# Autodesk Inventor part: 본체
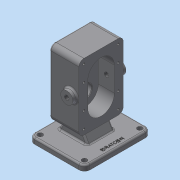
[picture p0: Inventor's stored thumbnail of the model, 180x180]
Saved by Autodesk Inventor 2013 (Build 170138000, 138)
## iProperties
Created: 2020-04
Part Number: 본체
Material: 일반
Document SubType Name: Modeling
Designer: dgall
Density: 1 g/cm^3
Author: dgall
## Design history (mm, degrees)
sketch "스케치1"
  geometry: L1 (-50, 60)-(50, 60); L2 (50, 60)-(50, -60); L3 (50, -60)-(-50, -60); L4 (-50, -60)-(-50, 60); 3 further points
  constraints: 8 end point, 2 midpoint, 2 parallel, 1 horizontal, 1 horizontal alignment, 1 perpendicular, 1 vertical alignment
  dimensions: "d0" = 100 distance of L1.start L1.end; "d2" = 120 distance of L1.end L2.end
extrude "돌출1" new body sketch "스케치1" stored distance "d3" = 10; taper "d4" = 0 deg
node "작업 평면1"
sketch "스케치2"
  geometry: L1 (145, -20)-(25, -20); L2 (25, -20)-(25, -100); L3 (25, -100)-(145, -100); L4 (145, -100)-(145, -20); L5 (-5, -120)-(-5, 0) reference; 2 further points
  constraints: 8 end point, 2 parallel, 1 horizontal, 1 horizontal alignment, 1 midpoint, 1 perpendicular
  dimensions: "d5" = 150 distance between parallel lines of L5 L4; "d6" = 80 distance of L3.end L1.start; "d7" = 120 distance of L1.start L1.end
extrude "돌출2" join sketch "스케치2" distance "d8" = 70; taper "d9" = 0 deg
extrude "돌출3" cut sketch "스케치2" distance "d10" = 17; taper "d11" = 0 deg
sketch "스케치3" dims "d31" = 10, "d38" = 10
  geometry: L1 (-25, -20)-(-145, -20) reference; L2 (-145, -20)-(-145, -100) reference; L3 (-145, -100)-(-25, -100) reference; L4 (-63, -84)-(-107, -84); L5 (-63, -36)-(-107, -36); A1 r 24 centre (-107, -60) between (-107, -36) and (-107, -84); A2 r 24 centre (-63, -60) between (-63, -84) and (-63, -36); 11 further points
  constraints: 4 end point, 4 point on circle, 3 horizontal, 2 centre point, 2 horizontal alignment, 2 midpoint, 2 parallel, 2 tangent, 1 equal radius, 1 vertical, 7 other
  dimensions: "d12" = 48 diameter of A1; "d14" = 44 distance of A2.centre A1.centre; "d15" = 9 distance from line of L2 point (-136, -91); "d16" = 9 distance from line of L3 point (-136, -91); "d17" = 29 horizontal distance of A1.centre point (-136, -91); "d20" = 62 distance of point (-136, -91) point (-136, -29); "d23" = 29 distance of point (-136, -91) point (-107, -91); "d28" = 44 distance of point (-107, -91) point (-63, -91); "d35" = 102 distance of point (-136, -91) point (-34, -91)
extrude "돌출4" cut sketch "스케치3" distance "d40" = 29; taper "d41" = 0 deg
hole "구멍1" sketch "스케치3" diameter "d42" = 4.134; stored, may be unused: countersink angle "d46" = 90 deg, drill point angle "d48" = 118 deg; dims "d43" = 10, "d44" = 4, "d45" = 2, "d47" = 12
sketch "스케치4"
  geometry: C1 r 19 at (-107, -60); A1 r 24 centre (-107, -60) between (-107, -36) and (-107, -84) reference; 1 further point
  constraints: 1 centre point, 1 coincident
  dimensions: "d49" = 38 diameter of C1
extrude "돌출5" join sketch "스케치4" distance "d51" = 41; taper "d52" = 0 deg
hole "구멍2" diameter "d55" = 28; stored, may be unused: countersink angle "d59" = 90 deg, drill point angle "d61" = 0 deg; dims "d53" = 10, "d54" = 10, "d56" = 10, "d57" = 28, "d58" = 7.3, "d60" = 7.3
sketch "스케치5"
  geometry: A1 r 24 centre (-107, -60) between (-107, -36) and (-107, -84) reference; 1 further point
hole "구멍3" sketch "스케치5" at (-107, -60) diameter "d62" = 17; stored, may be unused: countersink angle "d66" = 90 deg, drill point angle "d68" = 0 deg; dims "d63" = 10, "d64" = 25, "d65" = 15, "d67" = 50
sketch "스케치6"
  geometry: A1 r 24 centre (-63, -60) between (-63, -84) and (-63, -36) reference; 1 further point
hole "구멍4" sketch "스케치6" at (-63, -60) diameter "d69" = 25; stored, may be unused: countersink angle "d73" = 90 deg, drill point angle "d75" = 0 deg; dims "d70" = 10, "d71" = 25, "d72" = 15, "d74" = 15
sketch "스케치7"
  geometry: L1 (0, 120)-(0, 0) reference; L2 (-70, 150)-(30, 150) reference; C1 r 11 at (-14, 60); 1 further point
  constraints: 1 centre point
  dimensions: "d76" = 14 distance from line of L1 C1.centre; "d77" = 90 distance from line of L2 C1.centre; "d78" = 22 diameter of C1
extrude "돌출6" join sketch "스케치7" distance "d79" = 8; taper "d80" = 0 deg
sketch "스케치8"
  geometry: L1 (0, 120)-(0, 0) reference; L2 (30, -30)-(-70, -30) reference; C1 r 11 at (-14, 60); 1 further point
  constraints: 1 centre point
  dimensions: "d81" = 14 distance from line of L1 C1.centre; "d82" = 90 distance from line of L2 C1.centre; "d83" = 22 diameter of C1
extrude "돌출7" join sketch "스케치8" distance "d84" = 8; taper "d85" = 0 deg
hole "구멍5" diameter "d88" = 8.376; stored, may be unused: countersink angle "d92" = 90 deg, drill point angle "d94" = 0 deg; dims "d89" = 10, "d90" = 25, "d91" = 15, "d93" = 30, "d133" = 10, "d134" = 10
hole "구멍6" diameter "d97" = 8.376; stored, may be unused: countersink angle "d101" = 90 deg, drill point angle "d103" = 0 deg; dims "d98" = 10, "d99" = 25, "d100" = 15, "d102" = 30, "d135" = 10, "d136" = 10
sketch "스케치9"
  geometry: L1 (33, 25)-(-20, 25) reference; L2 (50, 5)-(-50, 5) reference; L3 (-20, 5)-(-8.453, 25); L4 (33, 5)-(21.453, 25); L5 (50, 5)-(50, -5) reference; 1 further point
  constraints: 4 end point, 4 point on line
  dimensions: "d104" = 53 distance of L4.start L3.start; "d105" = 17 distance from line of L5 L4.start; "d106" = 60 deg angle of L2 L3; "d107" = 60 deg angle of L2 L4
extrude "돌출8" join sketch "스케치9" stored distance "d108" = 48; taper "d109" = 0 deg
fillet "모깎기1" dims "d110" = 10
sketch "스케치10"
  geometry: A1 r 10 centre (-40, -50) between (-50, -50) and (-40, -60) reference; A2 r 10 centre (40, -50) between (40, -60) and (50, -50) reference; A3 r 10 centre (40, 50) between (50, 50) and (40, 60) reference; A4 r 10 centre (-40, 50) between (-40, 60) and (-50, 50) reference; 1 further point
hole "구멍7" sketch "스케치10" at (40, 50), (-40, 50), (-40, -50), (40, -50) diameter "d111" = 9; stored, may be unused: countersink angle "d115" = 90 deg, drill point angle "d117" = 0 deg; dims "d112" = 10, "d113" = 25, "d114" = 15, "d116" = 20
sketch "스케치11"
  geometry: L1 (-40, -60)-(40, -60) reference; L2 (50, -50)-(50, 50) reference; 2 further points
  constraints: 1 other
  dimensions: "d118" = 10 distance from line of L2 point (40, 0); "d119" = 60 distance from line of L1 point (40, 0)
feature "엠보싱1" sketch "스케치11" dims "d0" = 100, "d2" = 120, "d10" = 17, "d11" = 0, "d120" = 0.5, "d121" = 0
fillet "모깎기2" dims "d122" = 3
fillet "모깎기3" dims "d123" = 9
fillet "모깎기4" dims "d124" = 3
fillet "모깎기5" dims "d125" = 3
chamfer "모따기1" distance "d126" = 1; stored, may be unused: second distance "d127" = 2, angle "d128" = 45 deg
fillet "모깎기6" dims "d129" = 0.5
chamfer "모따기2" distance "d130" = 0.7; stored, may be unused: second distance "d131" = 2, angle "d132" = 30 deg
node "솔리드1"
